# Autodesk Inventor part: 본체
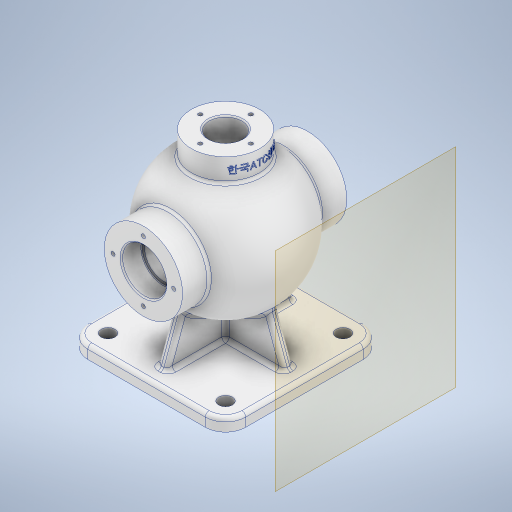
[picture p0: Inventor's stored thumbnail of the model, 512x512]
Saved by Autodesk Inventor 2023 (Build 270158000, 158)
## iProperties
Created: 2023-07
Part Number: 본체
Material: 알루미늄 6061
Document SubType Name: Modeling
Designer: Owner
Density: 2.7 g/cm^3
Appearance: 알루미늄 - 평지
Mass: 1528.71 g
Surface Area: 1177.44 cm^2
Volume: 566.189 cm^3
Author: Owner
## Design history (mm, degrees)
sketch "스케치1"
  geometry: L1 (62.5, 62.5)-(62.5, -62.5); L2 (62.5, -62.5)-(-62.5, -62.5); L3 (-62.5, -62.5)-(-62.5, 62.5); L4 (-62.5, 62.5)-(62.5, 62.5); L5 (62.5, 62.5)-(-62.5, -62.5); L6 (62.5, -62.5)-(-62.5, 62.5); 1 further point
  constraints: 12 end point, 2 midpoint, 2 parallel, 1 perpendicular, 1 vertical
  dimensions: "d0" = 125 distance of L1.end L2.end; "d1" = 125 distance of L2.end L3.end
extrude "돌출1" new body sketch "스케치1" distance "d2" = 10; taper "d3" = 0 deg
fillet "모깎기1" dims "d4" = 16
sketch "스케치3"
  geometry: L1 (85, 65)-(85, -65); L2 (10, 62.5)-(10, -62.5) reference; L3 (10, -62.5)-(0, -62.5) reference; L4 (0, -62.5)-(0, 62.5) reference; L5 (0, 62.5)-(10, 62.5) reference; L6 (85, 65)-(54, 65); L7 (54, -65)-(85, -65); L8 (54, 65)-(54, 44.215); L9 (54, -44.215)-(54, -65); A1 r 54 centre (85, 0) between (54, 44.215) and (54, -44.215); 3 further points
  constraints: 10 end point, 4 perpendicular, 2 midpoint, 2 point on circle, 1 centre point, 1 coincident, 1 collinear, 1 horizontal, 1 horizontal alignment, 1 vertical
  dimensions: "d8" = 130 distance of L1.start L1.end; "d9" = 108 diameter of A1; "d11" = 85 distance of point (0, 0) point (85, 0); "d12" = 31 distance of L1.start L6.end
revolve "회전1" sketch "스케치3" stored, may be unused: angle "d13" = 90 deg
sketch "스케치4"
  geometry: L1 (10, 50.5)-(85, 23.202); L2 (0, 62.5)-(10, 62.5) reference; L3 (85, -23.202)-(10, -50.5); L4 (10, 62.5)-(10, -62.5) reference; L5 (10, -62.5)-(0, -62.5) reference; L6 (0, -62.5)-(0, 62.5) reference; L7 (0, 62.5)-(10, 62.5) reference; L8 (54, 65)-(116, 65) reference; L9 (116, 65)-(116, 44.215) reference; L10 (116, -44.215)-(116, -65) reference; L11 (116, -65)-(54, -65) reference; L12 (54, -65)-(54, -44.215) reference; L13 (54, 44.215)-(54, 65) reference; L14 (85, -23.202)-(85, 23.202); A1 r 54 centre (85, 0) between (116, -44.215) and (116, 44.215) reference; A2 r 54 centre (85, 0) between (54, 44.215) and (54, -44.215) reference; 6 further points
  constraints: 6 end point, 3 midpoint, 2 point on line, 1 coincident
  dimensions: "d14" = 12 vertical distance of point (5, -62.5) L3.end; "d15" = 12 distance of L2.end L1.start; "d16" = 20 deg angle of L5 L3; "d17" = 20 deg angle of L1 L7
extrude "돌출2" join sketch "스케치4" stored distance "d18" = 8; taper "d19" = 0 deg
sketch "스케치6"
  geometry: L1 (4, 50.5)-(4, -50.5) reference; L2 (4, -50.5)-(-4, -50.5) reference; L3 (-4, -50.5)-(-4, 50.5) reference; L4 (-4, 50.5)-(4, 50.5) reference; L5 (-46.5, 62.5)-(46.5, 62.5) reference; L6 (62.5, 46.5)-(62.5, -46.5) reference; L7 (46.5, -62.5)-(-46.5, -62.5) reference; L8 (-62.5, -46.5)-(-62.5, 46.5) reference; C1 r 5.5 at (-46.5, 46.5); C2 r 5.5 at (46.5, 46.5); C3 r 5.5 at (-46.5, -46.5); C4 r 5.5 at (46.5, -46.5); A1 r 16 centre (-46.5, 46.5) between (-46.5, 62.5) and (-62.5, 46.5) reference; A2 r 16 centre (46.5, 46.5) between (62.5, 46.5) and (46.5, 62.5) reference; A3 r 16 centre (46.5, -46.5) between (46.5, -62.5) and (62.5, -46.5) reference; A4 r 16 centre (-46.5, -46.5) between (-62.5, -46.5) and (-46.5, -62.5) reference; 1 further point
  constraints: 4 centre point, 4 coincident
  dimensions: "d30" = 11 diameter of C1; "d31" = 11 diameter of C2; "d32" = 11 diameter of C3; "d33" = 11 diameter of C4
extrude "돌출4" cut sketch "스케치6" distance "d34" = 8; taper "d35" = 0 deg
sketch "스케치7"
  geometry: L1 (54, 65)-(116, 65) reference; L2 (116, 65)-(116, 44.215) reference; L3 (116, -44.215)-(116, -65) reference; L4 (116, -65)-(54, -65) reference; L5 (54, -65)-(54, -44.215) reference; L6 (46.034, -37.385)-(10, -50.5) reference; L7 (10, -50.5)-(10, -62.5) reference; L8 (10, -62.5)-(0, -62.5) reference; L9 (0, -62.5)-(0, 62.5) reference; L10 (0, 62.5)-(10, 62.5) reference; L11 (10, 62.5)-(10, 50.5) reference; L12 (10, 50.5)-(46.034, 37.385) reference; L13 (54, 44.215)-(54, 65) reference; L14 (54, 65)-(116, 65) reference; L15 (85, 65)-(85, -65); L16 (54, -65)-(116, -65) reference; L17 (102.5, 65)-(102.5, 49); L18 (102.5, 49)-(100, 49); L19 (100, 49)-(100, 41.364); L20 (-27.8, 0)-(166.8, 0) reference; L21 (102.5, -49)-(100, -49); L22 (100, -49)-(100, -41.364); L23 (102.5, -49)-(102.5, -65); L24 (102.5, 65)-(85, 65); L25 (102.5, -65)-(85, -65); A1 r 44 centre (85, 0) between (100, -41.364) and (100, 41.364); A2 r 54 centre (85, 0) between (46.034, -37.385) and (54, -44.215) reference; A3 r 54 centre (85, 0) between (54, 44.215) and (46.034, 37.385) reference; A4 r 54 centre (85, 0) between (116, -44.215) and (116, 44.215) reference; 6 further points
  constraints: 18 end point, 3 symmetric about line, 2 midpoint, 2 perpendicular, 2 point on circle, 2 point on line, 2 vertical, 1 centre point, 1 coincident, 1 collinear, 1 parallel
  dimensions: "d37" = 17.5 distance between parallel lines of L15 L17; "d38" = 15 distance between parallel lines of L15 L19; "d39" = 16 distance of L17.start L17.end; "d40" = 44 radius of A1
revolve "회전2" sketch "스케치7" stored, may be unused: angle "d41" = 90 deg
sketch "스케치8"
  geometry: C1 r 17.5 at (0, 0) reference; C2 r 31 at (0, 0) reference; 2 further points
  constraints: 1 vertical alignment
  dimensions: "d42" = 24 distance of C1.centre point (0, 24)
hole "구멍1" sketch "스케치8" at (0, 24) diameter "d43" = 3.242; stored, may be unused: countersink angle "d47" = 90 deg, drill point angle "d49" = 118 deg; dims "d44" = 12, "d45" = 4, "d46" = 2, "d48" = 15
node "작업 평면1"
sketch "스케치13"
  geometry: L1 (46.5, 10)-(-46.5, 10) reference; L2 (-50.5, 10)-(-41.174, 35.622); L3 (-62.5, 0)-(-62.5, 10) reference; 1 further point
  constraints: 2 end point, 1 point on line
  dimensions: "d74" = 12 distance from line of L2.start L3; "d75" = 20 deg angle of L2 L3
feature "리브1" sketch "스케치13" dims "d76" = 1, "d77" = 8, "d78" = 0, "d79" = 0, "d80" = 1, "d81" = 1
fillet "모깎기5" dims "d82" = 3
fillet "모깎기6" dims "d83" = 3
node "작업 평면4"
sketch "스케치14"
  geometry: C1 r 27 at (0, 0); 1 further point
  constraints: 1 centre point, 1 coincident
  dimensions: "d85" = 54 diameter of C1
extrude "돌출7" join sketch "스케치14" stored distance "d86" = 8; taper "d87" = 0 deg
sketch "스케치15"
  geometry: C1 r 13 at (0, 0); 1 further point
  constraints: 1 centre point, 1 coincident
  dimensions: "d88" = 26 diameter of C1
extrude "돌출8" cut sketch "스케치15" stored distance "d89" = 10; taper "d90" = 0 deg
sketch "스케치16"
  geometry: 2 further points
  constraints: 1 horizontal alignment
  dimensions: "d91" = 20 distance of point (0, 0) point (-20, 0)
hole "구멍3" sketch "스케치16" at (-20, 0) diameter "d92" = 3.242; stored, may be unused: countersink angle "d96" = 90 deg, drill point angle "d98" = 118 deg; dims "d93" = 9, "d94" = 4, "d95" = 2, "d97" = 11
fillet "모깎기7" dims "d102" = 3
chamfer "모따기1" distance "d103" = 1; stored, may be unused: second distance "d104" = 2, angle "d105" = 45 deg
fillet "모깎기8" dims "d106" = 0.6
chamfer "모따기2" distance "d107" = 1; stored, may be unused: second distance "d108" = 2, angle "d109" = 45 deg
node "작업 평면5"
sketch "스케치17"
  geometry: L1 (150, 27)-(150, -27) reference; 2 further points
  constraints: 1 horizontal alignment, 1 other
  dimensions: "d111" = 9 distance from line of point (141, 0) L1
feature "엠보싱1" sketch "스케치17" dims "d0" = 125, "d1" = 125, "d8" = 130, "d9" = 108, "d11" = 85, "d12" = 31, "d112" = 0.5, "d113" = 0
feature "˒耀˔耀˖耀˘耀˚耀˜耀˞耀ˠ耀" dims "d0" = 125, "d1" = 125, "d2" = 10, "d3" = 0, "d4" = 16, "d8" = 130, "d9" = 108, "d11" = 85, "d12" = 31, "d13" = 90 deg, "d14" = 12, "d15" = 12, "d16" = 20 deg, "d17" = 20 deg, "d18" = 8, "d19" = 0, "d30" = 11, "d31" = 11, "d32" = 11, "d33" = 11, "d34" = 8, "d35" = 0, "d36" = 88, "d37" = 17.5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
node "솔리드1"
pattern_circular "원형 패턴1" dims angle "d51" = 360 deg
mirror "미러1"
mirror "미러2"
pattern_circular "원형 패턴3" dims angle "d100" = 360 deg
node "절단 모서리 투영1"
node "절단 모서리 투영2"
node "절단 모서리 투영4"
node "절단 모서리 투영5"
node "절단 모서리 투영6"
feature "A9D066F2-1C7D-4E18-AEED-F7BC21143FA4" dims "d43" = 3.242, "d44" = 12, "d45" = 4, "d46" = 2, "d47" = 90 deg, "d48" = 15, "d49" = 118 deg
